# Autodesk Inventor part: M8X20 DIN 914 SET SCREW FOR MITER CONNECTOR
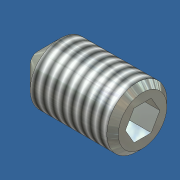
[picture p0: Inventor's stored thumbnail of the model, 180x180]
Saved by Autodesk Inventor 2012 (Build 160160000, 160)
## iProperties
Created: 2006-02
Part Number: M8X20 DIN 914 SET SCREW FOR MITER CONNECTOR
Material: Steel, Mild
Description: Hexagon Socket Set Screw
Document SubType Name: Modeling
Standard: DIN 914
Designer: Andy Moles
Standards Organization: DIN
Language: en-US
Size Designation: M8 x 12
Categories: <MemberInstance><Categories><Category DisplayName="Fasteners" InternalName="e4da775c-781d-43d5-af7c-5136215cf5a6" Mnemonic="FSTN"><Category DisplayName="Bolts"
Density: 7.86 g/cm^3
Mass: 6.57917 g
Surface Area: 6.08305 cm^2
Volume: 0.837045 cm^3
Author: Andy Moles
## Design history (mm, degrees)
revolve "Body" stored, may be unused: angle "d6" = 90 deg
sketch "Sketch2"
  geometry: L1 (-1.155, 2)-(1.155, 2); L2 (1.155, 2)-(2.309, 0); L3 (2.309, 0)-(1.155, -2); L4 (1.155, -2)-(-1.155, -2); L5 (-1.155, -2)-(-2.309, 0); L6 (-2.309, 0)-(-1.155, 2); 3 further points
  constraints: 12 end point, 1 coincident, 1 horizontal, 13 other
extrude "Slot" join sketch "Sketch2" taper "d7" = 0 deg; stored distance "d21" = 10
workaxis "Work Axis1"
workplane "Work Plane1"
body "Solid1"
feature "Thread" dims "d12" = 20 (= NLG), "d13" = 0
chamfer "Chamfer1" distance "d8" = 3 (computed from NND, SPD, FAWI); stored, may be unused: angle "d9" = 45 deg (= FAWI), second distance "d34" = 3 (computed from NND, SPD, FAWI)
chamfer "Chamfer2" distance "d10" = 0.76681 (= -0.5 x GD1 + 0.5 x NND); stored, may be unused: angle "d11" = 45 deg (= FAWI), second distance "d35" = 0.76681 (= -0.5 x GD1 + 0.5 x NND)
sketch "Sketch1"
  geometry: L1 (0, 0)-(13.667, 0); L2 (20, 2.309)-(20, 4); L3 (20, 4)-(0, 4); L4 (20, 2.309)-(15, 2.309); L5 (15, 2.309)-(13.667, 0); L6 (0, -0.4)-(0, 5.2) reference; L7 (0, 4)-(0, 0)
  constraints: 13 end point, 3 parallel, 1 collinear, 1 perpendicular, 1 point on line
  dimensions: "d0" = 5 distance of L2.start L4.end (= INTI); "d1" = 60 deg angle of L5 L1; "d2" = 8 diameter of L3 L1 (= NND); "d3" = 4.6188 diameter of L4 L1 (= 1.1547 x SW); "d5" = 20 distance from line of L2 L3.end (= NLG)
other parameters: "NND" = 8 [user parameter; used in 5 equation terms], "NLG" = 20 [user parameter; used in 2 equation terms], "INTI" = 5 [user parameter; used in 1 equation term], "FAWI" = 45 deg [user parameter; used in 4 equation terms], "SW" = 4 [user parameter; used in 2 equation terms], "GD1" = 6.46637 (= THREADDIA - 1.2269 x PTC) [user parameter; used in 2 equation terms], "d4" = 0, "FAWI1" = 45 deg [user parameter], "SPD" = 2 [user parameter; used in 2 equation terms], "d33" = 0, "d36" = 0, "GUL" = 0.76681 (= 0.61345 x PTC) [user parameter], "TPU" = 8 (computed from PTC) [user parameter], "TOA" = 30 deg [user parameter], "THREADDIA" = 8 [user parameter; used in 1 equation term], "PTC" = 1.25 [user parameter; used in 4 equation terms], "GAL" = 0.76681 (= 0.61345 x PTC) [user parameter], "E0" = 4.62 (= 1.155 x SW) [user parameter]
